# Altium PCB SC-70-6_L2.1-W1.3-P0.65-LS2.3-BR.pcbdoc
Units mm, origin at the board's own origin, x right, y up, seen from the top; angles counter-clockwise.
Board outline 16.2 x 15.14 mm, 2 copper layers (Top Layer, Bottom Layer), stack 0 mm thick; 1 components, 0 nets, 6 pads, 0 vias.
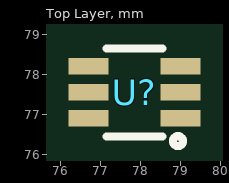
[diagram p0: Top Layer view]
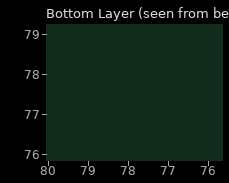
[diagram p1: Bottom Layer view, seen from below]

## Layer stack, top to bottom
Top Layer: signal copper (thickness not stored)
Bottom Layer: signal copper (thickness not stored)

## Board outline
86.051,69.85 69.85,69.85 69.85,84.994 86.051,84.994

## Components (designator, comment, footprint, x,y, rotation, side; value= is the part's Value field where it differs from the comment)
U? "" SC-70-6_L2.1-W1.3-P0.65-LS2.3-BR 77.85,77.544 r0 top

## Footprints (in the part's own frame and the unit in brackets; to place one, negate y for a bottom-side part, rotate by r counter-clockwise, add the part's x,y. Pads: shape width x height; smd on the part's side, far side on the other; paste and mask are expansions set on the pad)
SC-70-6_L2.1-W1.3-P0.65-LS2.3-BR [mm]
  rect 1x0.42 smd paste+0 mask+0.05: 1(1.15,-0.65) 2(1.15,0) 3(1.15,0.65) 4(-1.15,0.65) 5(-1.15,0) 6(-1.15,-0.65)
  silkscreen extent -0.7,-1.34 1.22,1.1

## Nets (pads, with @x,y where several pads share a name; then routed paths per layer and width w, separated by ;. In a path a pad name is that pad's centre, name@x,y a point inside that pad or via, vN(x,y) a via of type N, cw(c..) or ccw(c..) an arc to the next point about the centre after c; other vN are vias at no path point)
pads on no net: U?.1 U?.2 U?.3 U?.4 U?.5 U?.6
